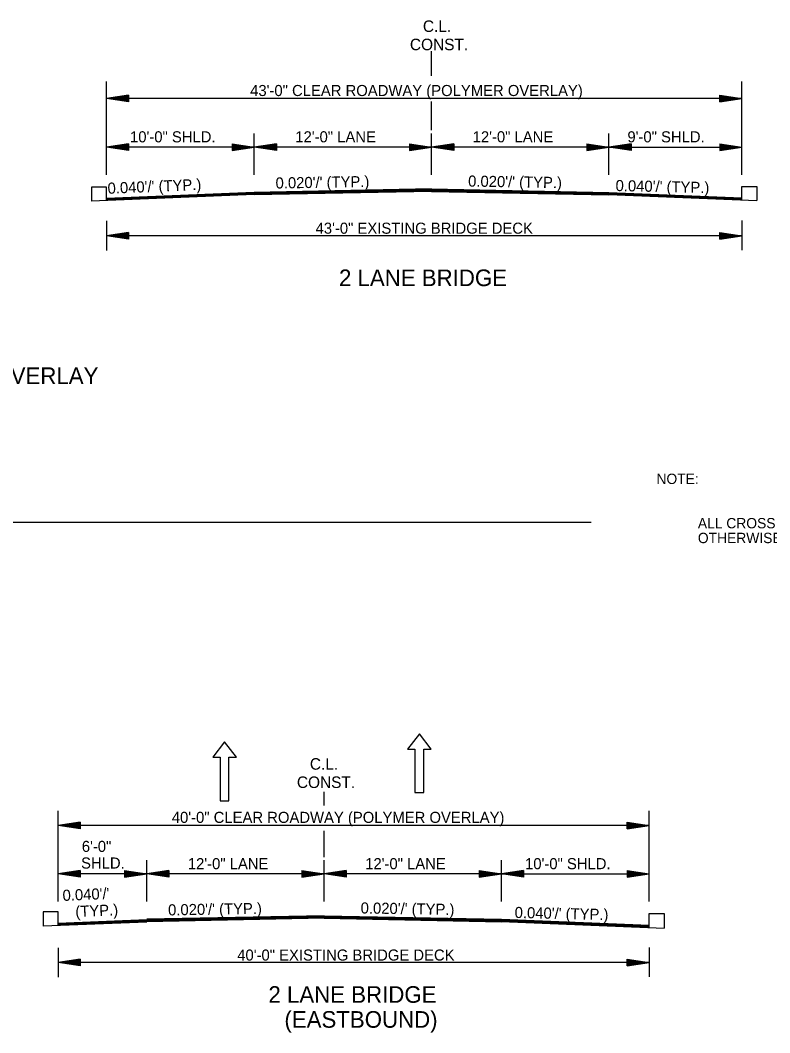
# Model space of a CAD drawing. Extents: x 550980 to 1930787, y -1972975 to 596640.
# Drawn here: x 551668 to 552175, y -1948982 to -1948297 of the extents above; entities that cross this region are included whole.
import ezdxf

# ---------------------------------------------------------------- set-up
doc = ezdxf.new("R2010")
doc.units = 0
for name, color, linetype in [('R_Border', 7, 'Continuous'), ('R_Border Notes', 7, 'Continuous'), ('R_Draft', 7, 'Continuous')]:
    doc.layers.add(name, color=color, linetype=linetype)

msp = doc.modelspace()

# ---------------------------------------------------------------- linework, layer by layer
at = {"layer": 'R_Border'}
for p, q in [((551715.95, -1948409.85), (551715.94, -1948419.36)), ((551726.12, -1948409.85), (551715.95, -1948409.85)), ((551726.12, -1948418.65), (551726.12, -1948409.85)), ((552156.12, -1948418.25), (552156.12, -1948409.45)), ((552156.12, -1948409.45), (552166.29, -1948409.45)), ((552166.29, -1948409.45), (552166.3, -1948418.96)), ((550992.91, -1948636.61), (552054.18, -1948636.61)), ((551683.22, -1948900.1), (551683.22, -1948909.92)), ((551693.39, -1948900.1), (551683.22, -1948900.1)), ((551693.39, -1948909.51), (551693.39, -1948900.1)), ((552093.39, -1948910.71), (552093.39, -1948901.3)), ((552093.39, -1948901.3), (552103.56, -1948901.3)), ((552103.56, -1948901.3), (552103.56, -1948911.12))]:
    msp.add_line(p, q, dxfattribs=at)
for points in [[(551945.87, -1948790.03), (551937.87, -1948779.65), (551929.87, -1948790.03), (551934.87, -1948790.03), (551934.87, -1948819.45), (551940.87, -1948819.45), (551940.87, -1948790.03)], [(551814.06, -1948795.58), (551806.06, -1948785.19), (551798.06, -1948795.58), (551803.06, -1948795.58), (551803.06, -1948825), (551809.06, -1948825), (551809.06, -1948795.58)]]:
    msp.add_lwpolyline(points, close=True, dxfattribs=at)
at = {"layer": 'R_Draft'}
for p, q in [((551946.12, -1948334.6), (551946.12, -1948317.97)), ((551726.12, -1948401.5), (551726.12, -1948338.47)), ((552156.12, -1948401.5), (552156.12, -1948338.47)), ((551741.12, -1948347.66), (551726.12, -1948349.91)), ((552156.12, -1948349.91), (551726.12, -1948349.91)), ((551741.12, -1948352.16), (551726.12, -1948349.91)), ((551741.12, -1948348.03), (551728.62, -1948349.91)), ((551741.12, -1948351.78), (551728.62, -1948349.91)), ((551741.12, -1948348.41), (551731.2, -1948349.91)), ((551741.12, -1948351.4), (551731.2, -1948349.91)), ((551741.12, -1948348.79), (551733.7, -1948349.91)), ((551741.12, -1948351.02), (551733.7, -1948349.91)), ((551741.12, -1948349.18), (551736.24, -1948349.91)), ((551741.12, -1948350.64), (551736.24, -1948349.91)), ((551741.12, -1948349.55), (551738.75, -1948349.91)), ((551741.12, -1948350.26), (551738.75, -1948349.91)), ((551741.12, -1948347.66), (551741.12, -1948352.16)), ((551946.12, -1948363.44), (551946.12, -1948351.99)), ((552141.12, -1948347.66), (552156.12, -1948349.91)), ((552141.12, -1948352.16), (552141.12, -1948347.66)), ((552141.12, -1948348.03), (552153.61, -1948349.91)), ((552141.12, -1948348.41), (552151.03, -1948349.91)), ((552141.12, -1948348.79), (552148.54, -1948349.91)), ((552141.12, -1948349.17), (552145.99, -1948349.91)), ((552141.12, -1948349.55), (552143.49, -1948349.91)), ((552141.12, -1948352.16), (552156.12, -1948349.91)), ((552141.12, -1948350.63), (552145.99, -1948349.91)), ((552141.12, -1948351.4), (552151.03, -1948349.91)), ((552141.12, -1948351.78), (552153.61, -1948349.91)), ((552141.12, -1948351.02), (552148.54, -1948349.91)), ((552141.12, -1948350.26), (552143.49, -1948349.91)), ((551946.12, -1948371.43), (551946.12, -1948363.44)), ((551826.12, -1948401.5), (551826.12, -1948373.55)), ((551946.12, -1948401.5), (551946.12, -1948373.55)), ((552066.12, -1948401.5), (552066.12, -1948373.55)), ((551741.12, -1948380.49), (551726.12, -1948382.74)), ((551741.12, -1948380.49), (551741.12, -1948384.99)), ((551811.12, -1948380.49), (551826.12, -1948382.74)), ((551811.12, -1948380.49), (551811.12, -1948384.99)), ((551841.12, -1948380.49), (551826.12, -1948382.74)), ((551841.12, -1948380.49), (551841.12, -1948384.99)), ((551931.12, -1948380.49), (551946.12, -1948382.74)), ((551931.12, -1948380.49), (551931.12, -1948384.99)), ((551961.12, -1948380.49), (551946.12, -1948382.74)), ((551961.12, -1948380.49), (551961.12, -1948384.99)), ((552051.12, -1948380.49), (552066.12, -1948382.74)), ((552051.12, -1948380.49), (552051.12, -1948384.99)), ((552081.12, -1948380.49), (552066.12, -1948382.74)), ((552081.12, -1948380.49), (552081.12, -1948384.99)), ((552141.12, -1948380.49), (552156.12, -1948382.74)), ((552141.12, -1948380.49), (552141.12, -1948384.99)), ((551826.12, -1948382.74), (551726.12, -1948382.74)), ((551741.12, -1948384.99), (551726.12, -1948382.74)), ((551741.12, -1948380.86), (551728.62, -1948382.74)), ((551741.12, -1948384.61), (551728.62, -1948382.74)), ((551741.12, -1948381.25), (551731.2, -1948382.74)), ((551741.12, -1948384.23), (551731.2, -1948382.74)), ((551741.12, -1948381.62), (551733.7, -1948382.74)), ((551741.12, -1948383.86), (551733.7, -1948382.74)), ((551741.12, -1948382.01), (551736.24, -1948382.74)), ((551741.12, -1948383.47), (551736.24, -1948382.74)), ((551741.12, -1948382.39), (551738.75, -1948382.74)), ((551741.12, -1948383.09), (551738.75, -1948382.74)), ((551811.12, -1948380.86), (551823.61, -1948382.74)), ((551811.12, -1948381.25), (551821.03, -1948382.74)), ((551811.12, -1948381.62), (551818.54, -1948382.74)), ((551811.12, -1948382.01), (551815.99, -1948382.74)), ((551811.12, -1948382.39), (551813.49, -1948382.74)), ((551811.12, -1948384.99), (551826.12, -1948382.74)), ((551811.12, -1948383.47), (551815.99, -1948382.74)), ((551811.12, -1948384.23), (551821.03, -1948382.74)), ((551811.12, -1948384.61), (551823.61, -1948382.74)), ((551811.12, -1948383.86), (551818.54, -1948382.74)), ((551811.12, -1948383.09), (551813.49, -1948382.74)), ((551946.12, -1948382.74), (551826.12, -1948382.74)), ((551841.12, -1948384.99), (551826.12, -1948382.74)), ((551841.12, -1948380.86), (551828.62, -1948382.74)), ((551841.12, -1948384.61), (551828.62, -1948382.74)), ((551841.12, -1948381.25), (551831.2, -1948382.74)), ((551841.12, -1948384.23), (551831.2, -1948382.74)), ((551841.12, -1948381.62), (551833.7, -1948382.74)), ((551841.12, -1948383.86), (551833.7, -1948382.74)), ((551841.12, -1948382.01), (551836.24, -1948382.74)), ((551841.12, -1948383.47), (551836.24, -1948382.74)), ((551841.12, -1948382.39), (551838.75, -1948382.74)), ((551841.12, -1948383.09), (551838.75, -1948382.74)), ((551931.12, -1948380.86), (551943.61, -1948382.74)), ((551931.12, -1948381.25), (551941.03, -1948382.74)), ((551931.12, -1948381.62), (551938.54, -1948382.74)), ((551931.12, -1948382.01), (551935.99, -1948382.74)), ((551931.12, -1948382.39), (551933.49, -1948382.74)), ((551931.12, -1948384.99), (551946.12, -1948382.74)), ((551931.12, -1948383.47), (551935.99, -1948382.74)), ((551931.12, -1948384.23), (551941.03, -1948382.74)), ((551931.12, -1948384.61), (551943.61, -1948382.74)), ((551931.12, -1948383.86), (551938.54, -1948382.74)), ((551931.12, -1948383.09), (551933.49, -1948382.74)), ((552066.12, -1948382.74), (551946.12, -1948382.74)), ((551961.12, -1948384.99), (551946.12, -1948382.74)), ((551961.12, -1948380.86), (551948.62, -1948382.74)), ((551961.12, -1948384.61), (551948.62, -1948382.74)), ((551961.12, -1948381.25), (551951.2, -1948382.74)), ((551961.12, -1948384.23), (551951.2, -1948382.74)), ((551961.12, -1948381.62), (551953.7, -1948382.74)), ((551961.12, -1948383.86), (551953.7, -1948382.74)), ((551961.12, -1948382.01), (551956.24, -1948382.74)), ((551961.12, -1948383.47), (551956.24, -1948382.74)), ((551961.12, -1948382.39), (551958.75, -1948382.74)), ((551961.12, -1948383.09), (551958.75, -1948382.74)), ((552051.12, -1948380.86), (552063.61, -1948382.74)), ((552051.12, -1948381.25), (552061.03, -1948382.74)), ((552051.12, -1948381.62), (552058.54, -1948382.74)), ((552051.12, -1948382.01), (552055.99, -1948382.74)), ((552051.12, -1948382.39), (552053.49, -1948382.74)), ((552051.12, -1948384.99), (552066.12, -1948382.74)), ((552051.12, -1948383.47), (552055.99, -1948382.74)), ((552051.12, -1948384.23), (552061.03, -1948382.74)), ((552051.12, -1948384.61), (552063.61, -1948382.74)), ((552051.12, -1948383.86), (552058.54, -1948382.74)), ((552051.12, -1948383.09), (552053.49, -1948382.74)), ((552066.12, -1948382.74), (552156.12, -1948382.74)), ((552081.12, -1948384.99), (552066.12, -1948382.74)), ((552081.12, -1948380.86), (552068.62, -1948382.74)), ((552081.12, -1948384.61), (552068.62, -1948382.74)), ((552081.12, -1948381.25), (552071.2, -1948382.74)), ((552081.12, -1948384.23), (552071.2, -1948382.74)), ((552081.12, -1948381.62), (552073.7, -1948382.74)), ((552081.12, -1948383.86), (552073.7, -1948382.74)), ((552081.12, -1948382.01), (552076.24, -1948382.74)), ((552081.12, -1948383.47), (552076.24, -1948382.74)), ((552081.12, -1948382.39), (552078.75, -1948382.74)), ((552081.12, -1948383.09), (552078.75, -1948382.74)), ((552141.12, -1948380.86), (552153.61, -1948382.74)), ((552141.12, -1948381.25), (552151.03, -1948382.74)), ((552141.12, -1948381.62), (552148.54, -1948382.74)), ((552141.12, -1948382.01), (552145.99, -1948382.74)), ((552141.12, -1948382.39), (552143.49, -1948382.74)), ((552141.12, -1948384.99), (552156.12, -1948382.74)), ((552141.12, -1948383.47), (552145.99, -1948382.74)), ((552141.12, -1948384.23), (552151.03, -1948382.74)), ((552141.12, -1948384.61), (552153.61, -1948382.74)), ((552141.12, -1948383.86), (552148.54, -1948382.74)), ((552141.12, -1948383.09), (552143.49, -1948382.74)), ((551826.12, -1948414.95), (551715.94, -1948419.36)), ((551826.12, -1948413.45), (551726.12, -1948417.45)), ((551826.12, -1948413.75), (551726.12, -1948417.75)), ((551826.12, -1948414.05), (551726.12, -1948418.05)), ((551826.12, -1948414.35), (551726.12, -1948418.35)), ((551826.12, -1948414.65), (551726.12, -1948418.65)), ((551946.12, -1948411.05), (551826.12, -1948413.45)), ((551946.12, -1948411.35), (551826.12, -1948413.75)), ((551946.12, -1948411.65), (551826.12, -1948414.05)), ((551946.12, -1948411.95), (551826.12, -1948414.35)), ((551946.12, -1948412.25), (551826.12, -1948414.65)), ((551946.12, -1948412.55), (551826.12, -1948414.95)), ((551946.12, -1948412.72), (551826.12, -1948415.12)), ((551946.12, -1948411.05), (552066.12, -1948413.45)), ((551946.12, -1948411.35), (552066.12, -1948413.75)), ((551946.12, -1948411.65), (552066.12, -1948414.05)), ((551946.12, -1948411.95), (552066.12, -1948414.35)), ((551946.12, -1948412.25), (552066.12, -1948414.65)), ((551946.12, -1948412.55), (552066.12, -1948414.95)), ((551946.12, -1948412.72), (552066.12, -1948415.12)), ((552066.12, -1948413.45), (552156.12, -1948417.05)), ((552066.12, -1948413.75), (552156.12, -1948417.35)), ((552066.12, -1948414.05), (552156.12, -1948417.65)), ((552066.12, -1948414.35), (552156.12, -1948417.95)), ((552066.12, -1948414.65), (552156.12, -1948418.25)), ((552066.12, -1948414.95), (552166.3, -1948418.96)), ((551726.12, -1948432.71), (551726.12, -1948452.71)), ((552156.12, -1948432.46), (552156.12, -1948452.46)), ((551741.12, -1948440.46), (551726.12, -1948442.71)), ((551741.12, -1948440.83), (551728.62, -1948442.71)), ((551741.12, -1948441.22), (551731.2, -1948442.71)), ((551741.12, -1948441.59), (551733.7, -1948442.71)), ((551741.12, -1948441.98), (551736.24, -1948442.71)), ((551741.12, -1948442.36), (551738.75, -1948442.71)), ((551741.12, -1948440.46), (551741.12, -1948444.96)), ((552141.12, -1948440.46), (552156.12, -1948442.71)), ((552141.12, -1948444.96), (552141.12, -1948440.46)), ((552141.12, -1948440.83), (552153.61, -1948442.71)), ((552141.12, -1948441.22), (552151.03, -1948442.71)), ((552141.12, -1948441.59), (552148.54, -1948442.71)), ((552141.12, -1948441.97), (552145.99, -1948442.71)), ((552141.12, -1948442.36), (552143.49, -1948442.71)), ((551741.12, -1948444.96), (551726.12, -1948442.71)), ((552156.12, -1948442.71), (551726.12, -1948442.71)), ((551741.12, -1948444.58), (551728.62, -1948442.71)), ((551741.12, -1948444.2), (551731.2, -1948442.71)), ((551741.12, -1948443.83), (551733.7, -1948442.71)), ((551741.12, -1948443.44), (551736.24, -1948442.71)), ((551741.12, -1948443.06), (551738.75, -1948442.71)), ((552141.12, -1948444.96), (552156.12, -1948442.71)), ((552141.12, -1948443.44), (552145.99, -1948442.71)), ((552141.12, -1948444.2), (552151.03, -1948442.71)), ((552141.12, -1948444.58), (552153.61, -1948442.71)), ((552141.12, -1948443.83), (552148.54, -1948442.71)), ((552141.12, -1948443.06), (552143.49, -1948442.71)), ((551873.39, -1948828.25), (551873.39, -1948818.95)), ((551693.39, -1948893.27), (551693.39, -1948831.78)), ((552093.39, -1948893.27), (552093.39, -1948831.78)), ((551708.39, -1948839.42), (551693.39, -1948841.67)), ((551708.39, -1948839.42), (551708.39, -1948843.92)), ((552078.39, -1948839.42), (552093.39, -1948841.67)), ((552078.39, -1948843.92), (552078.39, -1948839.42)), ((552093.39, -1948841.67), (551693.39, -1948841.67)), ((551708.39, -1948843.92), (551693.39, -1948841.67)), ((551708.39, -1948839.79), (551695.9, -1948841.67)), ((551708.39, -1948843.54), (551695.9, -1948841.67)), ((551708.39, -1948840.18), (551698.48, -1948841.67)), ((551708.39, -1948843.16), (551698.48, -1948841.67)), ((551708.39, -1948840.55), (551700.97, -1948841.67)), ((551708.39, -1948842.79), (551700.97, -1948841.67)), ((551708.39, -1948840.94), (551703.52, -1948841.67)), ((551708.39, -1948842.4), (551703.52, -1948841.67)), ((551708.39, -1948841.32), (551706.02, -1948841.67)), ((551708.39, -1948842.02), (551706.02, -1948841.67)), ((552063.39, -1948841.67), (551783.39, -1948841.67)), ((551873.39, -1948863.19), (551873.39, -1948845.43)), ((552078.39, -1948839.79), (552090.89, -1948841.67)), ((552078.39, -1948840.18), (552088.31, -1948841.67)), ((552078.39, -1948840.55), (552085.81, -1948841.67)), ((552078.39, -1948840.93), (552083.27, -1948841.67)), ((552078.39, -1948841.32), (552080.76, -1948841.67)), ((552078.39, -1948843.92), (552093.39, -1948841.67)), ((552078.39, -1948842.4), (552083.27, -1948841.67)), ((552078.39, -1948843.16), (552088.31, -1948841.67)), ((552078.39, -1948843.54), (552090.89, -1948841.67)), ((552078.39, -1948842.79), (552085.81, -1948841.67)), ((552078.39, -1948842.02), (552080.76, -1948841.67)), ((551753.39, -1948893.27), (551753.39, -1948865.31)), ((551873.39, -1948893.27), (551873.39, -1948865.31)), ((551993.39, -1948893.27), (551993.39, -1948865.31)), ((551708.39, -1948872.25), (551693.39, -1948874.5)), ((551708.39, -1948872.63), (551695.9, -1948874.5)), ((551708.39, -1948873.01), (551698.48, -1948874.5)), ((551708.39, -1948873.39), (551700.97, -1948874.5)), ((551708.39, -1948873.78), (551703.52, -1948874.5)), ((551708.39, -1948872.25), (551708.39, -1948876.75)), ((551738.39, -1948872.25), (551753.39, -1948874.5)), ((551738.39, -1948872.25), (551738.39, -1948876.75)), ((551738.39, -1948872.63), (551750.89, -1948874.5)), ((551738.39, -1948873.01), (551748.31, -1948874.5)), ((551738.39, -1948873.39), (551745.81, -1948874.5)), ((551738.39, -1948873.78), (551743.27, -1948874.5)), ((551768.39, -1948872.25), (551753.39, -1948874.5)), ((551768.39, -1948872.63), (551755.9, -1948874.5)), ((551768.39, -1948873.01), (551758.48, -1948874.5)), ((551768.39, -1948873.39), (551760.97, -1948874.5)), ((551768.39, -1948873.78), (551763.52, -1948874.5)), ((551768.39, -1948872.25), (551768.39, -1948876.75)), ((551858.39, -1948872.25), (551873.39, -1948874.5)), ((551858.39, -1948872.25), (551858.39, -1948876.75)), ((551858.39, -1948872.63), (551870.89, -1948874.5)), ((551858.39, -1948873.01), (551868.31, -1948874.5)), ((551858.39, -1948873.39), (551865.81, -1948874.5)), ((551858.39, -1948873.78), (551863.27, -1948874.5)), ((551888.39, -1948872.25), (551873.39, -1948874.5)), ((551888.39, -1948872.63), (551875.9, -1948874.5)), ((551888.39, -1948873.01), (551878.48, -1948874.5)), ((551888.39, -1948873.39), (551880.97, -1948874.5)), ((551888.39, -1948873.78), (551883.52, -1948874.5)), ((551888.39, -1948872.25), (551888.39, -1948876.75)), ((551978.39, -1948872.25), (551993.39, -1948874.5)), ((551978.39, -1948872.25), (551978.39, -1948876.75)), ((551978.39, -1948872.63), (551990.89, -1948874.5)), ((551978.39, -1948873.01), (551988.31, -1948874.5)), ((551978.39, -1948873.39), (551985.81, -1948874.5)), ((551978.39, -1948873.78), (551983.27, -1948874.5)), ((552008.39, -1948872.25), (551993.39, -1948874.5)), ((552008.39, -1948872.63), (551995.9, -1948874.5)), ((552008.39, -1948873.01), (551998.48, -1948874.5)), ((552008.39, -1948873.39), (552000.97, -1948874.5)), ((552008.39, -1948873.78), (552003.52, -1948874.5)), ((552008.39, -1948872.25), (552008.39, -1948876.75)), ((552078.39, -1948872.25), (552093.39, -1948874.5)), ((552078.39, -1948872.25), (552078.39, -1948876.75)), ((552078.39, -1948872.63), (552090.89, -1948874.5)), ((552078.39, -1948873.01), (552088.31, -1948874.5)), ((552078.39, -1948873.39), (552085.81, -1948874.5)), ((552078.39, -1948873.78), (552083.27, -1948874.5)), ((551753.39, -1948874.5), (551693.39, -1948874.5)), ((551708.39, -1948876.75), (551693.39, -1948874.5)), ((551708.39, -1948876.38), (551695.9, -1948874.5)), ((551708.39, -1948876), (551698.48, -1948874.5)), ((551708.39, -1948875.62), (551700.97, -1948874.5)), ((551708.39, -1948875.24), (551703.52, -1948874.5)), ((551708.39, -1948874.15), (551706.02, -1948874.5)), ((551708.39, -1948874.86), (551706.02, -1948874.5)), ((551738.39, -1948874.15), (551740.76, -1948874.5)), ((551738.39, -1948876.75), (551753.39, -1948874.5)), ((551738.39, -1948875.24), (551743.27, -1948874.5)), ((551738.39, -1948876), (551748.31, -1948874.5)), ((551738.39, -1948876.38), (551750.89, -1948874.5)), ((551738.39, -1948875.62), (551745.81, -1948874.5)), ((551738.39, -1948874.86), (551740.76, -1948874.5)), ((551873.39, -1948874.5), (551753.39, -1948874.5)), ((551768.39, -1948876.75), (551753.39, -1948874.5)), ((551768.39, -1948876.38), (551755.9, -1948874.5)), ((551768.39, -1948876), (551758.48, -1948874.5)), ((551768.39, -1948875.62), (551760.97, -1948874.5)), ((551768.39, -1948875.24), (551763.52, -1948874.5)), ((551768.39, -1948874.15), (551766.02, -1948874.5)), ((551768.39, -1948874.86), (551766.02, -1948874.5)), ((551858.39, -1948874.15), (551860.76, -1948874.5)), ((551858.39, -1948876.75), (551873.39, -1948874.5)), ((551858.39, -1948875.24), (551863.27, -1948874.5)), ((551858.39, -1948876), (551868.31, -1948874.5)), ((551858.39, -1948876.38), (551870.89, -1948874.5)), ((551858.39, -1948875.62), (551865.81, -1948874.5)), ((551858.39, -1948874.86), (551860.76, -1948874.5)), ((551993.39, -1948874.5), (551873.39, -1948874.5)), ((551888.39, -1948876.75), (551873.39, -1948874.5)), ((551888.39, -1948876.38), (551875.9, -1948874.5)), ((551888.39, -1948876), (551878.48, -1948874.5)), ((551888.39, -1948875.62), (551880.97, -1948874.5)), ((551888.39, -1948875.24), (551883.52, -1948874.5)), ((551888.39, -1948874.15), (551886.02, -1948874.5)), ((551888.39, -1948874.86), (551886.02, -1948874.5)), ((551978.39, -1948874.15), (551980.76, -1948874.5)), ((551978.39, -1948876.75), (551993.39, -1948874.5)), ((551978.39, -1948875.24), (551983.27, -1948874.5)), ((551978.39, -1948876), (551988.31, -1948874.5)), ((551978.39, -1948876.38), (551990.89, -1948874.5)), ((551978.39, -1948875.62), (551985.81, -1948874.5)), ((551978.39, -1948874.86), (551980.76, -1948874.5)), ((551993.39, -1948874.5), (552093.39, -1948874.5)), ((552008.39, -1948876.75), (551993.39, -1948874.5)), ((552008.39, -1948876.38), (551995.9, -1948874.5)), ((552008.39, -1948876), (551998.48, -1948874.5)), ((552008.39, -1948875.62), (552000.97, -1948874.5)), ((552008.39, -1948875.24), (552003.52, -1948874.5)), ((552008.39, -1948874.15), (552006.02, -1948874.5)), ((552008.39, -1948874.86), (552006.02, -1948874.5)), ((552078.39, -1948874.15), (552080.76, -1948874.5)), ((552078.39, -1948876.75), (552093.39, -1948874.5)), ((552078.39, -1948875.24), (552083.27, -1948874.5)), ((552078.39, -1948876), (552088.31, -1948874.5)), ((552078.39, -1948876.38), (552090.89, -1948874.5)), ((552078.39, -1948875.62), (552085.81, -1948874.5)), ((552078.39, -1948874.86), (552080.76, -1948874.5)), ((551753.39, -1948907.11), (551683.22, -1948909.92)), ((551753.39, -1948905.61), (551693.39, -1948908.01)), ((551753.39, -1948905.91), (551693.39, -1948908.31)), ((551753.39, -1948906.21), (551693.39, -1948908.61)), ((551753.39, -1948906.51), (551693.39, -1948908.91)), ((551753.39, -1948906.81), (551693.39, -1948909.21)), ((551873.39, -1948902.81), (551753.39, -1948905.21)), ((551873.39, -1948903.11), (551753.39, -1948905.51)), ((551873.39, -1948903.41), (551753.39, -1948905.81)), ((551873.39, -1948903.71), (551753.39, -1948906.11)), ((551873.39, -1948904.01), (551753.39, -1948906.41)), ((551873.39, -1948904.31), (551753.39, -1948906.71)), ((551873.39, -1948904.48), (551753.39, -1948906.88)), ((551873.39, -1948902.81), (551993.39, -1948905.21)), ((551873.39, -1948903.11), (551993.39, -1948905.51)), ((551873.39, -1948903.41), (551993.39, -1948905.81)), ((551873.39, -1948903.71), (551993.39, -1948906.11)), ((551873.39, -1948904.01), (551993.39, -1948906.41)), ((551873.39, -1948904.31), (551993.39, -1948906.71)), ((551873.39, -1948904.48), (551993.39, -1948906.88)), ((551993.39, -1948905.21), (552093.39, -1948909.21)), ((551993.39, -1948905.51), (552093.39, -1948909.51)), ((551993.39, -1948905.81), (552093.39, -1948909.81)), ((551993.39, -1948906.11), (552093.39, -1948910.11)), ((551993.39, -1948906.41), (552093.39, -1948910.41)), ((551993.39, -1948906.71), (552103.56, -1948911.12)), ((551693.39, -1948924.47), (551693.39, -1948944.47)), ((552093.39, -1948924.22), (552093.39, -1948944.22)), ((551708.39, -1948932.22), (551693.39, -1948934.47)), ((551708.39, -1948936.72), (551693.39, -1948934.47)), ((552093.39, -1948934.47), (551693.39, -1948934.47)), ((551708.39, -1948932.6), (551695.9, -1948934.47)), ((551708.39, -1948936.35), (551695.9, -1948934.47)), ((551708.39, -1948932.98), (551698.48, -1948934.47)), ((551708.39, -1948935.96), (551698.48, -1948934.47)), ((551708.39, -1948933.35), (551700.97, -1948934.47)), ((551708.39, -1948935.59), (551700.97, -1948934.47)), ((551708.39, -1948933.74), (551703.52, -1948934.47)), ((551708.39, -1948935.21), (551703.52, -1948934.47)), ((551708.39, -1948934.12), (551706.02, -1948934.47)), ((551708.39, -1948934.82), (551706.02, -1948934.47)), ((551708.39, -1948932.22), (551708.39, -1948936.72)), ((552078.39, -1948932.22), (552093.39, -1948934.47)), ((552078.39, -1948936.72), (552078.39, -1948932.22)), ((552078.39, -1948932.6), (552090.89, -1948934.47)), ((552078.39, -1948932.98), (552088.31, -1948934.47)), ((552078.39, -1948933.35), (552085.81, -1948934.47)), ((552078.39, -1948933.74), (552083.27, -1948934.47)), ((552078.39, -1948934.12), (552080.76, -1948934.47)), ((552078.39, -1948936.72), (552093.39, -1948934.47)), ((552078.39, -1948935.2), (552083.27, -1948934.47)), ((552078.39, -1948935.96), (552088.31, -1948934.47)), ((552078.39, -1948936.35), (552090.89, -1948934.47)), ((552078.39, -1948935.59), (552085.81, -1948934.47)), ((552078.39, -1948934.82), (552080.76, -1948934.47))]:
    msp.add_line(p, q, dxfattribs=at)

# ---------------------------------------------------------------- texts
at = {"layer": 'R_Border Notes'}
for s, p in [('NOTE: ', (552098.31, -1948610.72)), ('ALL CROSS SLOPES ARE TO MATCH EXISTING CROSS SLOPES UNLESS ', (552126.31, -1948640.72)), ('OTHERWISE APPROVED BY THE ENGINEER.', (552126.31, -1948650.72))]:
    msp.add_text(s, height=7, dxfattribs=at).set_placement(p)
at = {"layer": 'R_Draft'}
for s, height, p in [('C.L.', 7.8, (551940.27, -1948304.87)), ('CONST.', 7.8, (551931.49, -1948317.24)), ('43\'-0" CLEAR ROADWAY (POLYMER OVERLAY)', 7.5, (551823.38, -1948348.24)), ('10\'-0" SHLD.', 7.5, (551742.1, -1948379.57)), ('12\'-0" LANE', 7.5, (551853.93, -1948379.57)), ('12\'-0" LANE', 7.5, (551973.93, -1948379.57)), ('9\'-0" SHLD.', 7.5, (552078.64, -1948379.57)), ('43\'-0" EXISTING BRIDGE DECK', 7.5, (551867.67, -1948441.39)), ('2 LANE BRIDGE', 11.25, (551883.49, -1948476.84)), ('43 FT. CLEAR ROADWAY BRIDGE - POLYMER OVERLAY', 11.25, (551316.94, -1948543.08)), ('C.L.', 7.8, (551863.79, -1948804.01)), ('CONST.', 7.8, (551855.01, -1948816.38)), ('40\'-0" CLEAR ROADWAY (POLYMER OVERLAY)', 7.5, (551770.36, -1948840)), ('6\'-0"', 7.5, (551709.48, -1948859.64)), ('SHLD.', 7.5, (551708.98, -1948870.89)), ('12\'-0" LANE', 7.5, (551781.21, -1948871.33)), ('12\'-0" LANE', 7.5, (551901.21, -1948871.33)), ('10\'-0" SHLD.', 7.5, (552009.38, -1948871.33)), ('40\'-0" EXISTING BRIDGE DECK', 7.5, (551814.65, -1948933.15)), ('2 LANE BRIDGE ', 11.25, (551835.76, -1948961.71)), ('(EASTBOUND)', 11.25, (551846.57, -1948978.59))]:
    msp.add_text(s, height=height, dxfattribs=at).set_placement(p)
for s, rotation, p in [("  0.040'/' (TYP.)", 2.44797, (551721.5, -1948414.65)), ("0.020'/' (TYP.)", 0.97192, (551840.64, -1948410.84)), ("0.020'/' (TYP.)", 359.02808, (551970.82, -1948409.47)), ("0.040'/' (TYP.)", 358.68162, (552070.56, -1948412.48)), ("  0.040'/'", 2.44797, (551691.05, -1948893.04)), ("0.020'/' (TYP.)", 0.97192, (551767.91, -1948902.61)), ("0.020'/' (TYP.)", 359.02808, (551898.09, -1948901.24)), (' (TYP.)', 2.44797, (551702.47, -1948903.81)), ("0.040'/' (TYP.)", 358.68162, (552002.28, -1948904.29))]:
    msp.add_text(s, height=7.5, rotation=rotation, dxfattribs=at).set_placement(p)

doc.saveas('drawing.dxf')
